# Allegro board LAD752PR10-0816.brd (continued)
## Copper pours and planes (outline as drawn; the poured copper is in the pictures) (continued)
SPK_R-_CONN on TOP (solid shape): 28.04,14.23 28.04,13.72 27.82,13.49 26.87,13.49 26.74,13.62 26.74,14.38 27,14.64 27.64,14.64
SPK_R-_CONN on TOP (solid shape): 47.6,6.78 48.62,6.78 48.75,6.65 48.75,6.02 48.62,5.89 45.38,5.89 45.19,6.08 45.19,6.9 45.38,7.09 47.28,7.09
SPK_R-_CONN on BOTTOM (solid shape): 31.13,4.15 31.13,2.18 30.13,1.18 28.77,1.18 28.65,1.3 28.65,1.68 28.9,1.94 29.6,1.94 30.23,2.57 30.23,4.16 30.32,4.24 31.04,4.24
SPK_R-_CONN on BOTTOM (solid shape): 52.59,14.57 52.59,13.43 52.84,13.18 52.84,9.04 50.74,6.93 48.97,6.93 48.78,6.74 48.78,6.26 48.5,5.98 47.76,5.98 47.54,6.2 47.54,7.68 47.86,8 50.24,8 51.82,9.58 51.82,14.7 52.46,14.7
SPK_R-_CONN on IN3 (solid shape): 28.52,14.19 28.52,13.3 28.39,13.18 27.57,13.18 27.25,13.49 26.93,13.49 26.74,13.68 26.74,14.51 26.93,14.7 28.01,14.7
SPK_R-_CONN on IN3 (solid shape): 30.68,1.56 30.36,1.23 29.61,1.23 29.6,1.23 28.78,1.23 28.58,1.43 28.58,1.81 28.71,1.94 29.47,1.94 29.66,2.13 29.66,3.65 30.68,3.65
SPK_R-_CONN on IN4 (solid shape): 31.19,1.81 30.55,1.18 28.84,1.18 28.71,1.3 28.71,1.81 28.84,1.94 29.73,1.94 29.85,2.06 29.85,2.45 30.23,2.83 31.19,2.83
SPK_R-_CONN on IN4 (solid shape): 45.98,6.95 45.98,5.81 45.86,5.68 44.46,5.68 44.2,5.94 44.2,6.7 44.97,6.7 45.41,7.14 45.79,7.14
SW_1.2V on TOP (solid shape): outline of 340 points within 86.43,36.54 98.69,41.75
SW_1.2V on BOTTOM (solid shape): 91.57,43.26 91.57,43.1 90.8,42.33 90.55,42.08 90.55,41.87 90.18,41.5 89.23,41.5 89.16,41.56 89.16,42.39 89.29,42.51 90.09,42.51 90.1,42.5 90.69,43.08 90.69,43.24 90.75,43.3 91.53,43.3
SW_1.2V on BOTTOM (solid shape): outline of 83 points within 87.07,33.21 92.24,40.23
SW_1.2V on IN4 (solid shape): 90.93,42.84 90.93,42.52 90.26,41.86 90.26,41.45 89.86,41.05 89.2,41.05 89.2,41.91 89.86,42.57 90.17,42.57 90.56,42.96 90.81,42.96
SW_1.2V on IN4 (solid shape): 90.24,40.35 90.24,39.97 90.43,39.78 90.43,39.53 90.63,39.33 90.63,39.15 90.43,38.96 90.12,38.96 89.23,39.85 89.23,40.42 90.18,40.42
SW_+1VALWP on TOP (solid shape): 248.3,25.43 248.3,22.13 248.17,22.01 248.04,22.01 247.92,22.13 247.92,23.28 247.79,23.41 247.79,23.91 247.47,24.22 247.47,25.18 247.47,25.18 247.47,25.43 247.66,25.62 248.1,25.62
SW_+1VALWP on TOP (solid shape): 253.31,29.75 253.31,29.24 254.39,28.16 254.39,26.83 254.2,26.64 253.18,26.64 252.99,26.45 252.99,25.43 253.37,25.05 254.07,25.05 254.2,24.92 254.2,22.89 254.01,22.7 251.47,22.7 250.77,23.4 250.77,25.24 250.07,25.94 250.07,29.75 250.39,30.07 252.99,30.07
SW_+1VALWP on BOTTOM (solid shape): 253.91,29.53 253.91,25.43 253.88,25.43 253.63,25.18 253.12,25.18 252.74,24.8 252.74,22.98 252.57,22.81 251.17,22.81 250.71,23.28 250.71,24.29 249.82,25.18 249.82,29.69 250.33,30.19 253.25,30.19
SW_+1VALWP on IN4 (solid shape): 251.41,25.24 251.41,24.48 251.21,24.29 250.14,24.29 250.01,24.42 250.01,25.11 250.26,25.37 251.28,25.37
SW_+1VALWP on IN4 (solid shape): 248.94,25.24 248.99,25.19 248.99,24.29 248.29,23.59 248.29,23.32 248.14,23.17 247.96,23.17 247.78,23.35 247.78,25.18 247.97,25.37 248.94,25.37
TBT_SVR_IND on TOP (solid shape): 175.81,169.04 176.41,169.04 176.47,168.97 176.47,168.84 176.41,168.78 176.28,168.78 176.09,168.59 176.09,168.46 176.04,168.41 175.6,168.41 175.59,168.42 175.53,168.45 175.47,168.46 175.37,168.46 174.82,168.46 174.29,167.93 173.87,167.93 173.81,167.99 173.81,169.07 174.32,169.58 175.27,169.58
TBT_SVR_IND on BOTTOM (solid shape): 175.01,169.01 175.01,168.24 174.06,167.29 169.62,167.29 169.49,167.42 169.49,168.62 169.68,168.82 173.05,168.82 173.36,169.13 174.89,169.13
TBTA_CC1 on TOP: 191.42,173.12 191.59,172.96 191.59,172.65 191.42,172.49 191.22,172.49 190.89,172.82 190.89,174.42 191.99,175.52 191.99,176.77 192.12,176.89 192.54,176.89 192.71,176.73 192.71,175.33 191.42,174.05
UG_3V on TOP (solid shape): 53.79,29.5 53.79,28.99 53.48,28.67 52.52,28.67 52.4,28.8 52.4,29.31 52.46,29.37 52.97,29.37 53.29,29.69 53.6,29.69
UG_3V on BOTTOM (solid shape): 56.65,44.17 56.65,43.92 56.46,43.73 56.01,43.73 55,44.74 55,44.93 55.06,45 55.82,45
UG_3V on IN4 (solid shape): 57.98,42.96 57.98,42.71 57.54,42.26 57.28,42.26 56.33,43.22 56.33,43.34 55.63,44.04 55.63,44.49 55.82,44.68 56.27,44.68
UG_3V on IN4 (solid shape): 53.41,30.45 53.29,30.32 53.29,30.07 53.79,29.56 53.79,29.24 53.29,28.73 52.84,28.73 52.14,29.43 52.14,30.51 52.4,30.77 53.41,30.77
UG_5V on TOP (solid shape): 47.32,37.24 47.32,36.23 47.13,36.04 46.49,36.04 46.3,36.23 46.3,37.22 46.41,37.33 47.23,37.33
UG_5V on BOTTOM (solid shape): 52.78,44.91 52.78,44.84 52.17,44.23 52.17,43.79 51.96,43.59 51.63,43.59 51.52,43.7 51.52,44.75 51.75,44.98 52.7,44.98
UG_5V on IN4 (solid shape): 47.13,37.18 47.32,36.99 47.32,36.23 47.13,36.04 46.3,36.04 46.11,36.23 46.11,38.07 47.13,38.07
UG_5V on IN4 (solid shape): 52.01,44.55 52.01,43.47 51.19,42.65 50.81,42.65 50.36,43.09 50.36,43.53 51.51,44.68 51.89,44.68
UG_+1VALWP on TOP (solid shape): 254.64,25.88 255.22,25.88 255.34,25.75 255.34,25.43 255.23,25.32 254.78,25.32 254.74,25.28 253.46,25.28 253.25,25.5 253.25,26.26 253.37,26.38 254.14,26.38
UG_+1VALWP on TOP (solid shape): 247.6,23.78 247.6,23.4 247.66,23.34 247.66,23.21 247.79,23.09 247.79,22.13 247.66,22.01 247.47,22.01 247.41,22.07 247.41,22.9 246.71,23.59 246.71,24.23 246.83,24.35 247.02,24.35
UG_+1VALWP on IN4 (solid shape): 247.64,25.8 247.64,23.46 247.5,23.33 247.05,23.33 246.6,23.78 246.6,26.2 246.73,26.32 247.11,26.32
UG_+1VALWP on IN4 (solid shape): 255.28,26.19 255.28,25.43 255.09,25.24 254.2,25.24 253.75,25.69 253.75,26.32 254.33,26.89 254.58,26.89
N4123408 on BOTTOM (solid shape): 59,45.94 59,44.16 58.87,44.04 58.37,44.04 58.05,44.36 58.05,45.94 58.17,46.07 58.87,46.07
N4123550 on TOP (solid shape): 44.27,31.21 44.27,30.32 44.4,30.19 45.28,30.19 45.41,30.07 45.41,29.12 45.28,28.99 43.51,28.99 43.13,29.37 43.13,31.21 43.32,31.4 44.08,31.4
N4123582 on TOP (solid shape): 44.52,32.61 44.52,31.72 44.46,31.66 41.92,31.66 41.8,31.77 41.8,32.79 41.76,32.83 41.86,32.93 44.2,32.93
N4124695 on BOTTOM (solid shape): 49.67,45.69 49.67,44.23 49.54,44.1 48.9,44.1 48.78,44.23 48.78,45.75 48.97,45.94 49.41,45.94
N16788038 on TOP (solid shape): 69.6,40.74 69.6,39.91 69.41,39.72 68.84,39.72 67.7,38.58 66.49,38.58 66.43,38.64 66.43,39.59 66.56,39.72 67.51,39.72 68.02,40.23 68.02,40.86 68.08,40.93 69.41,40.93
N17847188 on BOTTOM (solid shape): 199.98,75.7 199.98,75.27 200.5,74.75 200.5,73.26 199.99,72.93 200.5,72.6 200.5,72.32 200.25,72.08 199.43,72.08 199.43,71.52 199.24,71.52 199.24,72.08 198.77,72.08 198.77,72.36 198.93,72.66 198.77,72.95 198.77,73.53 198.49,73.81 198.06,73.81 198.03,73.84 198.03,74.31 198.01,74.4 197.96,74.48 197.96,76.08 198.02,76.14 199.54,76.14
N17848703 on BOTTOM (solid shape): 200.53,79.93 200.53,78.66 200.43,78.56 200.16,78.56 200.16,78.9 199.14,78.9 198.7,79.34 198.05,79.34 197.86,79.53 197.86,80.15 197.91,80.2 200.26,80.2
N18456772 on TOP (solid shape): 60.78,24.42 60.78,24.16 59.89,23.27 59.06,23.27 58.99,23.34 58.99,23.59 59.37,23.97 59.75,23.97 60.33,24.55 60.65,24.55
N18456859 on TOP (solid shape): 63.13,23.34 63.13,21.24 63,21.11 62.43,21.11 62.37,21.18 62.37,22.13 62.56,22.32 62.56,22.77 62.37,22.96 62.37,23.53 62.43,23.59 62.87,23.59
N19529526 on TOP (solid shape): 40.65,8.88 40.65,8.22 39.93,7.49 37.17,7.49 37.11,7.56 37.11,7.68 37.17,7.75 38.11,7.75 38.19,7.83 38.52,7.83 38.74,8.06 38.77,8.06 38.96,8.13 39.08,8.39 39.15,8.41 39.25,8.41 39.44,8.6 39.44,8.92 39.59,9.07 40.46,9.07
N19529526 on BOTTOM (solid shape): 41.06,8.56 41.06,6.86 40.65,6.45 40.01,7.08 40.01,7.72 39.51,8.22 39.51,8.99 39.62,9.1 40.52,9.1
N19529527 on TOP (solid shape): 34.34,6.65 34.34,5.84 34.42,5.76 34.42,4.99 34.55,4.86 34.6,4.8 34.66,4.75 34.8,4.61 35.06,4.61 35.12,4.55 35.12,3.66 35.05,3.6 34.33,3.6 34.25,3.68 34.25,4.65 34.14,4.75 34.14,6.65 34.19,6.7 34.29,6.7
N19529528 on TOP (solid shape): 33.95,6.65 33.95,5.79 33.99,5.75 33.99,4.7 34.1,4.59 34.1,3.7 34.09,3.69 33.45,3.69 33.43,3.71 33.43,4.85 33.72,5.14 33.72,5.8 33.73,5.81 33.73,6.64 33.8,6.7 33.9,6.7
N19529529 on TOP (solid shape): 30.95,7.68 30.95,7.56 30.88,7.49 30.06,7.49 29.56,6.99 29.56,6.66 29.41,6.51 28.77,6.51 28.65,6.64 28.65,7.46 28.72,7.53 29.21,7.53 29.42,7.75 30.88,7.75
N20474318 on TOP (solid shape): 31.31,2.64 31.31,1.3 31.19,1.18 30.68,1.18 30.62,1.24 30.62,2.7 30.68,2.76 31.19,2.76
N20474322 on TOP (solid shape): 35.66,3.21 35.66,2.36 36.08,1.94 36.08,1.37 36.01,1.3 35.51,1.3 35.44,1.37 35.44,1.91 34.97,2.38 34.97,3.23 35.02,3.28 35.58,3.28
N20474324 on BOTTOM (solid shape): 40.59,5.11 40.59,4.99 40.17,4.57 39.83,4.62 39.6,4.37 39.58,4.35 38.9,4.35 38.84,4.41 38.84,4.92 38.92,5 39.65,5 40.14,5.49 40.2,5.49
N24654525 on TOP (solid shape): 203.99,64.09 203.99,63.72 203.46,63.72 203.46,63.21 203.99,63.21 203.99,62.92 203.46,62.92 203.46,62.41 203.99,62.41 203.99,61.97 203.14,61.13 202.27,61.13 201.97,60.82 201.97,60.68 201.9,60.62 201.39,60.62 201.03,60.97 201.03,62.32 201.31,62.6 201.33,62.6 201.64,62.6 202.22,63.18 202.22,64.04 202.31,64.13 203.94,64.13
N26590633 on BOTTOM (solid shape): 23.44,53.75 23.44,51.64 22.56,50.76 22.56,50.59 22.55,50.58 22.55,49.5 22.93,49.12 22.93,47.92 22.8,47.79 19.23,47.79 19.16,47.8 19.09,47.79 18.59,47.79 18.52,47.8 18.46,47.79 18.15,47.79 18.12,47.75 17.5,47.75 17.39,47.87 17.39,48.38 17.43,48.41 18.88,48.41 19.03,48.57 19.04,48.64 19.04,49.02 19.35,49.34 21.35,49.34 21.47,49.46 21.47,51.09 20.77,51.78 20.39,51.78 20.14,51.53 19.06,51.53 19,51.59 19,53.12 19.12,53.25 20.07,53.25 20.96,54.13 23.06,54.13
N26590633 on IN4 (solid shape): outline of 96 points within 19.47,48.07 23.99,52.94
N29425467 on BOTTOM (solid shape): 174.46,141.7 174.46,140.55 174.59,140.43 178.33,140.43 178.46,140.3 178.46,140.28 178.82,139.91 178.82,135.99 178.58,135.74 174.94,135.74 174.53,136.15 173.78,136.15 173.5,136.44 173.5,141.76 173.62,141.89 174.27,141.89
N29425497 on BOTTOM (solid shape): 166.12,141.67 166.12,140.53 166.24,140.4 169.99,140.4 170.12,140.27 170.12,137.63 170.57,137.18 170.61,137.18 170.62,137.17 172.77,137.17 173.03,136.9 173.03,133.43 172.81,133.2 170.05,133.2 169.6,133.65 169.6,135.17 167.14,137.64 165.86,137.64 165.15,138.35 165.15,141.73 165.28,141.86 165.93,141.86
N29425633 on BOTTOM (solid shape): 157.79,141.77 157.79,140.58 157.91,140.45 161.66,140.45 161.75,140.36 161.75,138.28 159.41,135.93 159.41,134.16 158.71,133.46 155.33,133.46 155.16,133.62 155.16,137.1 155.3,137.24 156.48,137.24 156.87,137.63 156.87,141.76 156.96,141.85 157.7,141.85
N29435109 on BOTTOM (solid shape): 184.92,138.84 184.92,138.21 185.56,137.57 185.56,135.54 185.18,135.16 181.87,135.16 181.78,135.26 181.78,137.29 182.25,137.76 182.25,139.17 182.38,139.29 184.47,139.29
N29435333 on BOTTOM (solid shape): 150.1,144.99 150.1,143.84 150.23,143.72 153.98,143.72 154.04,143.65 154.04,142.81 153.97,142.74 153.97,142.16 154.04,142.08 154.04,139.55 153.93,139.44 149.42,139.44 149.41,139.45 149.11,139.45 148.97,139.59 148.97,144.88 149.26,145.18 149.91,145.18
N29435335 on TOP (solid shape): 186.25,136.43 186.25,135.48 185.94,135.16 184.67,135.16 183.71,134.21 182.7,134.21 182.7,134.72 182.76,134.78 183.59,134.78 184.41,135.6 184.41,136.37 184.54,136.49 186.19,136.49
N29436554 on BOTTOM (solid shape): 141.77,144.96 141.77,143.82 141.9,143.69 145.64,143.69 145.77,143.56 145.77,139.59 145.6,139.42 141.42,139.42 141.17,139.67 141.17,141.07 140.81,141.43 140.81,145.02 140.93,145.15 141.58,145.15
N31425872 on BOTTOM (solid shape): 160.9,146.61 160.9,145.97 160.25,145.32 160.25,144.68 160.12,144.55 160,144.55 159.93,144.62 159.93,146.61 159.99,146.67 160.84,146.67
N31425874 on BOTTOM (solid shape): 162.14,148.04 162.17,148 162.17,147.44 162.12,147.39 159.97,147.39 159.92,147.44 159.92,147.99 159.97,148.04 162.1,148.04
N31425876 on BOTTOM (solid shape): 162.19,146.58 162.19,145.9 161.98,145.69 161.51,145.69 161.23,145.41 161.23,144.58 161.17,144.51 160.98,144.51 160.91,144.58 160.91,145.61 161.23,145.93 161.23,146.59 161.28,146.64 162.12,146.64
N31432086 on BOTTOM (solid shape): 170.47,147.99 170.5,147.95 170.5,147.39 170.45,147.34 168.31,147.34 168.25,147.39 168.25,147.94 168.31,147.99 170.43,147.99
N31432111 on BOTTOM (solid shape): 169.23,146.55 169.23,145.92 168.58,145.26 168.58,144.63 168.45,144.5 168.33,144.5 168.26,144.57 168.26,146.56 168.32,146.62 169.17,146.62
N31432114 on BOTTOM (solid shape): 170.52,146.53 170.52,145.85 170.31,145.64 169.84,145.64 169.56,145.36 169.56,144.53 169.5,144.46 169.31,144.46 169.24,144.53 169.24,145.56 169.56,145.87 169.56,146.54 169.62,146.59 170.45,146.59
N31436196 on BOTTOM (solid shape): 178.81,148.01 178.85,147.98 178.85,147.42 178.8,147.37 176.65,147.37 176.6,147.42 176.6,147.96 176.65,148.02 178.78,148.02
N31436215 on BOTTOM (solid shape): 177.58,146.58 177.58,145.94 176.92,145.29 176.92,144.66 176.8,144.53 176.67,144.53 176.61,144.59 176.61,146.59 176.66,146.64 177.51,146.64
N31436218 on BOTTOM (solid shape): 178.86,146.55 178.86,145.87 178.66,145.67 178.19,145.67 177.9,145.38 177.9,144.55 177.84,144.49 177.65,144.49 177.59,144.55 177.59,145.58 177.9,145.9 177.9,146.56 177.96,146.62 178.8,146.62
N31439632 on BOTTOM (solid shape): 146.12,151.28 146.16,151.24 146.16,150.68 146.11,150.63 143.96,150.63 143.91,150.68 143.91,151.23 143.96,151.28 146.09,151.28
N31439653 on BOTTOM (solid shape): 144.89,149.84 144.89,149.21 144.23,148.55 144.23,147.92 144.11,147.79 143.98,147.79 143.92,147.86 143.92,149.85 143.97,149.91 144.82,149.91
N31439658 on BOTTOM (solid shape): 146.17,149.82 146.17,149.14 145.97,148.93 145.5,148.93 145.21,148.65 145.21,147.81 145.15,147.75 144.96,147.75 144.9,147.81 144.9,148.85 145.21,149.16 145.21,149.82 145.27,149.88 146.11,149.88
N31452286 on BOTTOM (solid shape): 153.22,149.87 153.22,149.23 152.57,148.58 152.57,147.94 152.44,147.82 152.31,147.82 152.25,147.88 152.25,149.88 152.3,149.93 153.15,149.93
N31452288 on BOTTOM (solid shape): 154.45,151.3 154.49,151.27 154.49,150.71 154.44,150.66 152.29,150.66 152.24,150.71 152.24,151.25 152.29,151.3 154.42,151.3
N31452290 on BOTTOM (solid shape): 154.5,149.84 154.5,149.33 154.12,148.96 153.83,148.96 153.55,148.67 153.55,147.84 153.48,147.78 153.29,147.78 153.23,147.84 153.23,148.87 153.55,149.19 153.55,149.85 153.6,149.91 154.44,149.91
N31466143 on TOP (solid shape): 80.84,28.42 82.05,28.42 82.24,28.23 82.24,27.15 82.11,27.02 79.57,27.02 79.45,27.15 79.45,28.67 79.51,28.73 80.53,28.73
N31494164 on BOTTOM (solid shape): 185.88,146.52 185.88,145.9 185.87,145.89 183.77,145.89 183.74,145.93 183.74,146.53 183.75,146.54 185.86,146.54
N31494196 on BOTTOM (solid shape): 184.65,145.13 184.65,144.55 184.54,144.43 184.54,144.43 184.09,143.99 184.09,143.98 184.09,142.97 184.03,142.91 183.84,142.91 183.77,142.97 183.77,144.39 183.74,144.43 183.74,145.15 183.77,145.18 184.6,145.18
N31494209 on BOTTOM (solid shape): 185.89,145.14 185.89,144.51 185.78,144.41 185.72,144.41 185.11,143.8 185.11,143.8 185.11,143.48 184.54,142.91 184.35,142.91 184.28,142.97 184.28,143.86 184.29,143.86 184.96,144.53 184.96,145.12 185.01,145.17 185.86,145.17
N32074224 on BOTTOM (solid shape): 273.03,159.58 273.03,158.62 272.9,158.5 272.27,158.5 272.01,158.24 272.01,157.73 271.88,157.61 271.38,157.61 271.19,157.8 271.19,159.58 271.31,159.7 272.9,159.7
N32074541 on TOP (solid shape): 266.44,172.75 266.44,171.06 266.31,170.94 265.28,170.94 265.24,170.98 265.24,171.63 265.16,171.71 264.41,171.71 264.26,171.87 264.26,172.7 264.42,172.86 266.33,172.86
N32187709 on BOTTOM (solid shape): 239.75,40.58 239.75,37.76 239.12,37.12 236.59,37.12 236.38,36.91 235.07,36.91 234.94,37.04 234.94,38.15 235,38.21 238.02,38.21 238.48,38.67 238.48,40.7 238.58,40.8 239.53,40.8
N32187730 on BOTTOM (solid shape): 232.13,36.02 232.13,35.29 231.94,35.1 230.6,35.1 230.51,35.19 230.51,36.09 230.58,36.15 232,36.15
N32220030 on TOP (solid shape): 246.96,25.37 246.96,24.61 246.9,24.54 246.26,24.54 246.01,24.29 246.01,23.59 245.82,23.4 244.93,23.4 244.86,23.46 244.86,25.05 245.31,25.5 246.83,25.5
N32220048 on BOTTOM (solid shape): 256.14,24.36 256.14,23.76 256.04,23.65 255.41,23.65 255.23,23.48 255.23,22.85 255.2,22.82 254.18,22.82 254.11,22.89 254.11,24.51 254.19,24.58 255.91,24.58
N32278456 on BOTTOM (solid shape): 276.81,57.69 276.81,55.91 276.68,55.79 275.34,55.79 275.22,55.91 275.22,56.74 275.34,56.86 276.04,56.86 276.17,56.99 276.17,57.71 276.23,57.77 276.72,57.77
N32278468 on BOTTOM (solid shape): 270.3,56.68 270.3,55.48 270.24,55.42 268.96,55.42 268.9,55.48 268.9,56.71 269.04,56.85 270.14,56.85
N32278470 on BOTTOM (solid shape): 272.2,59.81 272.96,59.81 272.96,60.72 274.32,60.72 274.35,60.69 274.35,58.38 274.98,57.75 275.79,57.75 275.85,57.69 275.85,57.12 275.73,56.99 274.73,56.99 273.15,55.41 270.56,55.41 270.5,55.47 270.5,60.52 270.69,60.72 272.2,60.72
N32278548 on BOTTOM (solid shape): 269.85,49.24 269.85,48.61 269.73,48.48 267.63,48.48 267.5,48.61 267.5,49.31 267.57,49.37 269.73,49.37
N32320016 on BOTTOM (solid shape): 269.5,52.28 269.5,51.37 269.62,51.25 270.01,51.25 270.1,51.33 270.1,52.3 270.14,52.34 270.26,52.34 270.31,52.3 270.31,51 270.26,50.96 270.01,50.96 269.88,50.83 269.88,49.99 269.77,49.88 268.93,49.88 268.87,49.94 268.87,50.51 269.3,50.94 269.3,52.28 269.36,52.34 269.44,52.34
N32320046 on BOTTOM (solid shape): 269.1,52.27 269.1,51 268.61,50.51 268.61,50.01 268.55,49.94 267.6,49.94 267.47,50.07 267.47,50.71 267.58,50.82 268.3,50.82 268.89,51.41 268.89,52.26 268.95,52.32 269.05,52.32
N32336439 on TOP (solid shape): 254.17,59.84 254.17,58.06 254.04,57.93 252.55,57.93 252.52,57.96 252.52,58.92 252.55,58.95 253.28,58.95 253.47,59.14 253.47,59.84 253.53,59.9 254.11,59.9
N32336483 on BOTTOM (solid shape): 250.23,57.71 250.23,56.51 250.17,56.45 248.88,56.45 248.82,56.5 248.82,57.71 249.09,57.98 249.96,57.98
N32336487 on TOP (solid shape): 253.34,60.5 253.34,60.12 253.09,59.87 253.09,59.23 253.03,59.17 252.52,59.17 252.39,59.3 252.39,60.44 252.58,60.63 253.22,60.63
N32336487 on BOTTOM (solid shape): 250.42,60.25 251.18,60.25 251.18,61.14 253.59,61.14 254.19,60.54 254.19,57.56 253.09,56.45 250.47,56.45 250.43,56.5 250.43,57.73 250.15,58 250.15,58 250,58.15 248.52,58.15 248.1,58.57 248.1,60.67 248.57,61.14 250.42,61.14
N32336677 on BOTTOM (solid shape): 250.26,50.38 250.26,49.75 250.13,49.62 248.03,49.62 247.91,49.75 247.91,50.45 247.97,50.51 250.13,50.51
N32336681 on BOTTOM (solid shape): 249.03,53.3 249.03,51.76 248.99,51.72 248.99,51.14 248.92,51.08 248.1,51.08 248.03,51.14 248.03,51.78 248.04,51.78 248.17,51.78 248.83,52.44 248.83,53.3 248.88,53.35 248.98,53.35
N32337023 on BOTTOM (solid shape): 250.23,53.3 250.23,51.17 250.16,51.1 249.32,51.1 249.22,51.2 249.22,53.29 249.29,53.35 249.38,53.35 249.43,53.29 249.43,52.35 249.56,52.22 249.91,52.22 250.03,52.34 250.03,53.3 250.08,53.35 250.18,53.35
N32338871 on BOTTOM (solid shape): 233.05,50.32 233.05,49.69 232.99,49.63 230.89,49.63 230.77,49.75 230.77,50.45 230.83,50.51 232.86,50.51
N32338879 on BOTTOM (solid shape): 231.89,53.3 231.89,51.77 231.85,51.72 231.85,51.15 231.78,51.09 230.96,51.09 230.89,51.15 230.89,51.72 230.96,51.78 231.02,51.78 231.69,52.45 231.69,53.3 231.74,53.36 231.84,53.36
N32339247 on BOTTOM (solid shape): 232.29,53.31 232.29,52.36 232.42,52.23 232.76,52.23 232.89,52.35 232.89,53.3 232.95,53.36 233.05,53.36 233.09,53.31 233.09,51.17 233.03,51.1 232.14,51.1 232.08,51.16 232.08,53.29 232.15,53.36 232.24,53.36
N32339676 on TOP (solid shape): 237.05,59.74 237.05,57.96 236.93,57.84 235.44,57.84 235.4,57.87 235.4,58.82 235.44,58.85 236.17,58.85 236.36,59.04 236.36,59.74 236.42,59.8 236.99,59.8
N32339714 on TOP (solid shape): 236.23,60.41 236.23,60.03 235.97,59.77 235.97,59.14 235.91,59.07 235.4,59.07 235.28,59.2 235.28,60.34 235.47,60.53 236.1,60.53
N32339714 on BOTTOM (solid shape): 233.28,60.26 234.04,60.26 234.04,61.14 236.46,61.14 237.05,60.55 237.05,57.56 235.94,56.45 233.34,56.45 233.28,56.51 233.28,57.77 233.04,58.01 231.53,58.01 230.96,58.58 230.96,60.67 231.43,61.14 233.28,61.14
N32339716 on BOTTOM (solid shape): 233.1,57.71 233.1,56.51 233.04,56.45 231.74,56.45 231.68,56.51 231.68,57.72 231.85,57.88 232.93,57.88
N32822458 on BOTTOM (solid shape): 122.62,115.61 122.62,114.99 123.39,114.22 123.39,113.53 123.33,113.48 122.8,113.48 122.78,113.5 122.78,113.86 121.88,114.76 121.88,115.61 121.96,115.7 122.53,115.7
N32822969 on BOTTOM (solid shape): 119.7,113.7 119.7,112.81 119.64,112.75 117.92,112.75 117.8,112.87 117.8,113.7 117.86,113.76 119.64,113.76
N33651095 on TOP (solid shape): 244.79,60.41 244.79,60.03 244.53,59.77 244.53,59.18 244.48,59.13 243.91,59.13 243.84,59.2 243.84,60.34 244.03,60.53 244.66,60.53
N33651095 on BOTTOM (solid shape): 241.85,60.26 242.61,60.26 242.61,61.12 245.06,61.12 245.63,60.55 245.63,57.56 244.52,56.46 241.92,56.46 241.86,56.52 241.86,57.71 241.44,58.13 239.98,58.13 239.53,58.58 239.53,60.67 239.98,61.12 241.85,61.12
N33651113 on BOTTOM (solid shape): 241.63,50.39 241.63,49.69 241.56,49.63 239.47,49.63 239.34,49.75 239.34,50.45 239.4,50.51 241.5,50.51
N33651117 on BOTTOM (solid shape): 241.67,57.71 241.67,56.52 241.61,56.46 240.29,56.46 240.23,56.52 240.23,57.77 240.42,57.96 241.42,57.96
N33651127 on BOTTOM (solid shape): 240.86,53.31 240.86,52.36 240.99,52.23 241.37,52.23 241.45,52.31 241.45,53.29 241.52,53.36 241.63,53.36 241.67,53.32 241.67,51.14 241.62,51.1 240.72,51.1 240.66,51.16 240.66,53.29 240.74,53.37 240.8,53.37
N33651327 on BOTTOM (solid shape): 240.47,53.3 240.47,51.77 240.42,51.72 240.42,51.15 240.36,51.09 239.53,51.09 239.47,51.15 239.47,51.72 239.53,51.78 239.59,51.78 240.26,52.45 240.26,53.3 240.32,53.36 240.41,53.36
N33651387 on TOP (solid shape): 245.61,59.74 245.61,58.1 245.46,57.94 244.03,57.94 243.96,58 243.96,58.8 244.01,58.85 244.73,58.85 244.92,59.04 244.92,59.74 244.98,59.8 245.55,59.8
N33654422 on BOTTOM (solid shape): 224.4,58.77 224.4,57.51 224.34,57.46 223.04,57.46 222.99,57.51 222.99,58.74 223.21,58.96 224.2,58.96
N33654426 on BOTTOM (solid shape): 224.35,51.48 224.35,51.14 224.34,51.13 224.34,50.74 224.23,50.62 222.2,50.62 222.07,50.75 222.07,51.45 222.14,51.51 224.32,51.51
N33654440 on TOP (solid shape): 227.39,61.37 227.39,61.06 227.3,60.96 227.3,60.6 227.28,60.59 227.28,60.17 226.74,60.17 226.58,61.33 226.7,61.45 227.31,61.45
N33654440 on BOTTOM (solid shape): 224.58,61.25 225.35,61.25 225.35,62.11 227.79,62.11 228.36,61.54 228.36,58.56 227.25,57.45 224.64,57.45 224.59,57.5 224.59,58.78 224.28,59.09 222.75,59.09 222.27,59.57 222.27,61.67 222.71,62.11 224.58,62.11
N33654466 on BOTTOM (solid shape): 223.6,54.3 223.6,53.35 223.7,53.25 224.04,53.25 224.19,53.4 224.19,54.29 224.26,54.35 224.34,54.35 224.41,54.29 224.41,52.17 224.34,52.11 223.48,52.11 223.39,52.19 223.39,54.29 223.47,54.37 223.54,54.37
N33654622 on BOTTOM (solid shape): 223.2,54.3 223.2,52.76 223.15,52.72 223.15,52.14 223.12,52.11 222.24,52.11 222.2,52.14 222.2,52.78 222.22,52.79 222.34,52.79 222.99,53.45 222.99,54.3 223.05,54.35 223.14,54.35
N33654648 on TOP (solid shape): 228.37,60.75 228.37,59.03 228.29,58.96 226.79,58.96 226.72,59.02 226.72,59.83 226.75,59.86 227.48,59.86 227.68,60.05 227.68,60.75 227.74,60.81 228.31,60.81
N72585933 on TOP (solid shape): 98.5,36.1 98.5,34.45 97.93,33.88 97.1,33.88 96.97,34 96.97,34.77 96.66,35.08 96.66,36.1 96.78,36.23 98.37,36.23

Small or netless copper shapes (teardrops, artwork), in the pictures only: 107 on TOP, 315 on BOTTOM, 1 on IN1, 2 on IN3

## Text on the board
Ref Des/Silkscreen Bottom: FOR | C17 | SPEAKER | MK | BL | HDD/SSD | TRON LIGHT L | TRON LIGHT R | DC IN | BATTERY | JDIMM1 | JDIMM2 | KB BL | TP | KB | RTC | WLAN | SSD-2 | ONLY FOR DDR4
User.Comments: LA-D752P | 2016-08-16 | 2017-08-16 | Minjia | BAP10
Ref Des/Silkscreen Top: CPU FAN | GPU FAN | USB BOARD | TOBII | EDP | POWER | LOGO
GND4: GND4
GND5: GND5
BODY_CENTER: GND | +5VS | +5VALW | +3VALW | +3VS | +VCCGT | +VCC_CORE | +VCCSA | +VCCIO | +3VS_SSD | +1VALW | +1.5V_MEN_GFX | +VGA_CORE | B+
COMPVAL_TYPE_BOTTOM: LAYER | NAME | L3 | L1 | L2 | L5 | L4 | L6 | L7 | L11 | L8 | L9 | L10 | L12 | LA-D752P | GND4 | GND2 | GND3 | GND5 | TOP | GND1 | IN2 | IN3 | IN1 | VCC | IN4 | BOT | LS-XXXXP
User.44: Width/space | 3.6 / 3.5 | 3.5 / 4.5 | 3.5 / 5.1 | 95 ohm
User.45: FIGURE | SIZE | 8.0 | 20.0 | 22.0 | 30.0 | 35.0 | 36.0 | 39.0 | 90.0 | 118.0 | 142.0 | 150.0 | 26.0 | 43.0 | 47.0 | 63.0 | 49.0x28.0 | 55.0x24.0 | 63.0x35.0 | 67.0x24.0 | 69.0x28.0 | 75.0x24.0 | 75.0x28.0 | 79.0x31.0 | 94.0x24.0 | 94.0x28.0 | 161.0x142.0 | 165.0x142.0 | 33.0x26.0 | DRILL CHART: TOP to BOTTOM | ALL UNITS ARE IN MILS | TOLERANCE | +3.0/-3.0 | +2.0/-2.0 | PLATED | NON-PLATED | QTY | 11048 | 10 | 19 | 1 | 8 | 9 | 5 | 14 | 2 | 6 | 4
